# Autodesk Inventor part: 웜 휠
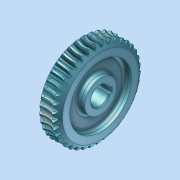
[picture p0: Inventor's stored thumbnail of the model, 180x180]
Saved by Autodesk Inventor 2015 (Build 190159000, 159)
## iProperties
Created: 2026-02
Part Number: 웜 휠
Material: 일반
Document SubType Name: Modeling
Designer: Administrator
Density: 1 g/cm^3
Appearance: 기본값
Author: Administrator
Author: jhkim
Creation Date: 2026-01-30
Sending System: Autodesk Inventor 2026
Preprocessor: ST-DEVELOPER v20.1
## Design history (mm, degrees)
node "웜 휠1"
node "솔리드1"
node "기준1"
